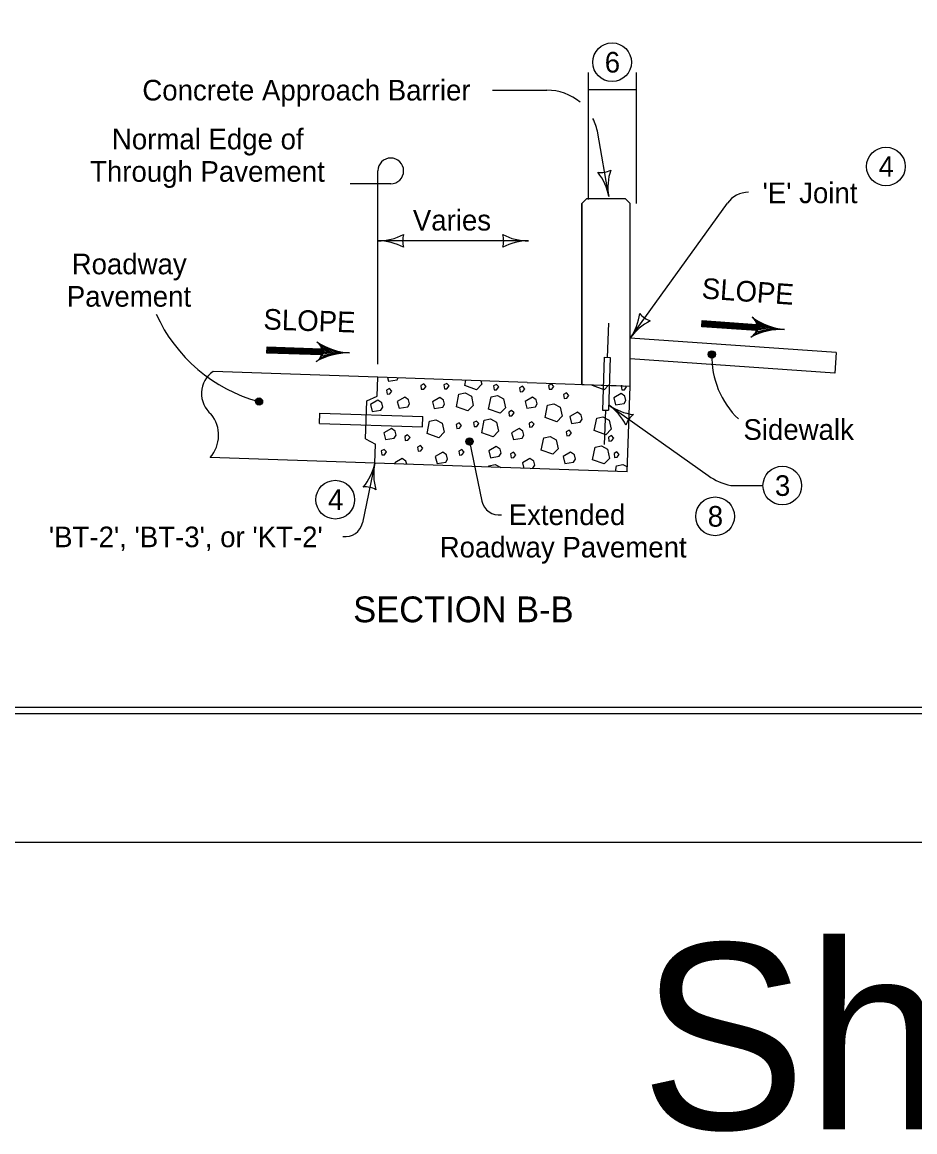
# Model space of a CAD drawing. Extents: x 10028 to 81668, y 6395 to 11634.
# Drawn here: x 10833 to 11525, y 7600 to 8460 of the extents above; entities that cross this region are included whole.
import ezdxf

# ---------------------------------------------------------------- set-up
doc = ezdxf.new("R2010")
doc.units = 0
for name, color, linetype in [('Default', 7, 'Continuous'), ('dsnCellElements', 7, 'Continuous'), ('dsnstdblockInterim', 7, 'Continuous'), ('dsnStdDimension', 7, 'Continuous'), ('dsnStdTextLabel', 7, 'Continuous'), ('ShtPlotIdentification', 7, 'Continuous')]:
    doc.layers.add(name, color=color, linetype=linetype)

msp = doc.modelspace()

# ---------------------------------------------------------------- linework, layer by layer
at = {"layer": 'Default'}
msp.add_lwpolyline([(10132.52, 9944.02), (13267.53, 9944.02), (13267.53, 7924.02), (10132.52, 7924.02)], close=True, dxfattribs=at)
msp.add_lwpolyline([(10132.52, 9944.02), (13267.53, 9944.02), (13267.53, 7924.02), (10132.52, 7924.02)], close=True, dxfattribs=at)
at = {"layer": 'dsnCellElements'}
for points in [[(11266.54, 8179.61), (11303.9, 8178.3), (11303.9, 8319.91), (11300.29, 8323.36), (11270.12, 8323.36), (11266.54, 8319.98)], [(11115.07, 8175.07), (11115.53, 8172.01), (11117.51, 8172.16), (11119.2, 8174.3), (11117.36, 8176.29)], [(11141.53, 8178.81), (11141.98, 8175.75), (11143.97, 8175.9), (11145.65, 8178.04), (11143.82, 8180.03)], [(11159.38, 8179.11), (11159.83, 8176.05), (11161.82, 8176.2), (11163.5, 8178.34), (11161.67, 8180.33)], [(11197.95, 8178.35), (11198.4, 8175.29), (11200.39, 8175.44), (11202.07, 8177.59), (11200.24, 8179.57)], [(11218.11, 8176.98), (11218.57, 8173.92), (11220.56, 8174.08), (11222.24, 8176.22), (11220.4, 8178.2)], [(11240.61, 8178.81), (11241.07, 8175.75), (11243.05, 8175.9), (11244.74, 8178.04), (11242.9, 8180.03)], [(11102.58, 8163.95), (11103.96, 8158.6), (11110.69, 8159.67), (11112.06, 8161.97), (11111.3, 8165.18), (11108.39, 8167.32)], [(11123.33, 8166.42), (11124.71, 8161.07), (11131.43, 8162.14), (11132.81, 8164.43), (11132.05, 8167.65), (11129.14, 8169.79)], [(11150.55, 8166.12), (11151.92, 8160.76), (11158.65, 8161.83), (11160.03, 8164.13), (11159.26, 8167.34), (11156.36, 8169.48)], [(11171.12, 8171.88), (11176.02, 8172.95), (11180.76, 8170.35), (11182.28, 8163.32), (11178.16, 8159.04), (11169.13, 8162.25)], [(11196.17, 8169.98), (11201.06, 8171.05), (11205.8, 8168.45), (11207.33, 8161.42), (11203.2, 8157.14), (11194.18, 8160.35)], [(11222.41, 8166.42), (11223.79, 8161.07), (11230.52, 8162.14), (11231.89, 8164.43), (11231.13, 8167.65), (11228.22, 8169.79)], [(11252.28, 8171.68), (11252.74, 8168.62), (11254.72, 8168.78), (11256.41, 8170.92), (11254.57, 8172.91)], [(11291.13, 8169.16), (11292.51, 8163.8), (11299.24, 8164.87), (11300.61, 8167.17), (11299.85, 8170.38), (11296.94, 8172.52)], [(11209.72, 8158.17), (11210.18, 8155.11), (11212.17, 8155.26), (11213.85, 8157.4), (11212.01, 8159.39)], [(11239.93, 8163.48), (11244.82, 8164.55), (11249.56, 8161.96), (11251.09, 8154.92), (11246.96, 8150.64), (11237.94, 8153.85)], [(11257.15, 8154.56), (11258.52, 8149.21), (11265.25, 8150.28), (11266.63, 8152.58), (11265.86, 8155.79), (11262.96, 8157.93)], [(11148.41, 8151.05), (11153.31, 8152.12), (11158.05, 8149.52), (11159.57, 8142.49), (11155.45, 8138.21), (11146.42, 8141.42)], [(11169.12, 8148.53), (11169.58, 8145.47), (11171.56, 8145.62), (11173.25, 8147.76), (11171.41, 8149.75)], [(11182.5, 8149.91), (11182.96, 8146.85), (11184.95, 8147), (11186.63, 8149.15), (11184.8, 8151.13)], [(11190.76, 8151.74), (11195.65, 8152.81), (11200.39, 8150.22), (11201.92, 8143.18), (11197.79, 8138.9), (11188.77, 8142.11)], [(11225.47, 8149.45), (11225.93, 8146.39), (11227.92, 8146.55), (11229.6, 8148.69), (11227.76, 8150.67)], [(11277.94, 8153.37), (11282.83, 8154.44), (11287.57, 8151.84), (11289.1, 8144.81), (11284.97, 8140.53), (11275.95, 8143.74)], [(11112.93, 8142.11), (11114.31, 8136.76), (11121.04, 8137.83), (11122.41, 8140.12), (11121.65, 8143.33), (11118.74, 8145.47)], [(11129.09, 8139.18), (11129.55, 8136.12), (11131.54, 8136.27), (11133.22, 8138.42), (11131.38, 8140.4)], [(11212.01, 8142.11), (11213.39, 8136.76), (11220.12, 8137.83), (11221.49, 8140.12), (11220.73, 8143.33), (11217.82, 8145.47)], [(11254.38, 8142.84), (11254.84, 8139.78), (11256.82, 8139.94), (11258.51, 8142.08), (11256.67, 8144.06)], [(11139.08, 8130.95), (11139.54, 8127.89), (11141.52, 8128.04), (11143.21, 8130.18), (11141.37, 8132.17)], [(11236.86, 8138.23), (11241.76, 8139.3), (11246.5, 8136.7), (11248.03, 8129.67), (11243.9, 8125.39), (11234.88, 8128.6)], [(11276.69, 8130.8), (11281.59, 8131.87), (11286.33, 8129.27), (11287.85, 8122.23), (11283.73, 8117.95), (11274.7, 8121.16)], [(11287.02, 8138.64), (11287.48, 8135.58), (11289.47, 8135.74), (11291.15, 8137.88), (11289.31, 8139.86)], [(11110.94, 8127.97), (11111.4, 8124.92), (11113.39, 8125.07), (11115.07, 8127.21), (11113.24, 8129.2)], [(11152.84, 8123.61), (11154.22, 8118.26), (11160.94, 8119.33), (11162.32, 8121.62), (11161.56, 8124.83), (11158.65, 8126.97)], [(11171.06, 8127.85), (11171.52, 8124.79), (11173.51, 8124.94), (11175.19, 8127.08), (11173.36, 8129.07)], [(11194.3, 8128.1), (11195.67, 8122.75), (11202.4, 8123.82), (11203.78, 8126.12), (11203.01, 8129.33), (11200.11, 8131.47)], [(11211.22, 8125.69), (11211.68, 8122.63), (11213.66, 8122.78), (11215.35, 8124.92), (11213.51, 8126.91)], [(11251.92, 8123.61), (11253.3, 8118.26), (11260.03, 8119.33), (11261.4, 8121.62), (11260.64, 8124.83), (11257.73, 8126.97)], [(11291.37, 8126.06), (11291.83, 8123), (11293.82, 8123.15), (11295.5, 8125.29), (11293.66, 8127.28)]]:
    msp.add_lwpolyline(points, close=True, dxfattribs=at)
for points in [[(11115.72, 8184.87), (11116.45, 8182.02)], [(11123.18, 8183.09), (11124.07, 8184.58)], [(11116.45, 8182.02), (11123.18, 8183.09)], [(11175.62, 8178.65), (11176.47, 8182.75)], [(11184.64, 8175.44), (11175.62, 8178.65)], [(11188.77, 8179.72), (11184.64, 8175.44)], [(11188.2, 8182.34), (11188.77, 8179.72)], [(11274.7, 8178.65), (11274.84, 8179.32)], [(11283.73, 8175.44), (11274.7, 8178.65)], [(11287.05, 8178.89), (11283.73, 8175.44)], [(11297.37, 8178.53), (11297.03, 8178.35)], [(11297.03, 8178.35), (11297.49, 8175.29)], [(11297.49, 8175.29), (11299.47, 8175.44)], [(11299.47, 8175.44), (11301.16, 8177.59)], [(11301.16, 8177.59), (11300.38, 8178.43)], [(11127.15, 8122.23), (11121.34, 8118.87)], [(11121.34, 8118.87), (11121.58, 8117.96)], [(11130.06, 8120.09), (11127.15, 8122.23)], [(11130.64, 8117.65), (11130.06, 8120.09)], [(11194.07, 8115.43), (11194.28, 8116.42)], [(11194.28, 8116.42), (11199.17, 8117.49)], [(11199.17, 8117.49), (11203.53, 8115.1)], [(11226.23, 8122.23), (11220.42, 8118.87)], [(11220.42, 8118.87), (11221.55, 8114.48)], [(11229.14, 8120.09), (11226.23, 8122.23)], [(11226.7, 8114.3), (11228.53, 8114.59)], [(11228.53, 8114.59), (11229.9, 8116.88)], [(11229.9, 8116.88), (11229.14, 8120.09)], [(11292.45, 8112), (11293.36, 8116.42)], [(11293.36, 8116.42), (11298.25, 8117.49)], [(11298.25, 8117.49), (11301.71, 8115.6)]]:
    msp.add_lwpolyline(points, dxfattribs=at)
at = {"layer": 'dsnstdblockInterim'}
for points in [[(10132.52, 9939.02), (13267.52, 9939.02), (13267.52, 7929.02), (10132.52, 7929.02)], [(10132.53, 9944.02), (13267.52, 9944.02), (13267.52, 7924.02), (10132.53, 7924.02)]]:
    msp.add_lwpolyline(points, close=True, dxfattribs=at)
at = {"layer": 'dsnStdDimension'}
msp.add_lwpolyline([(10028.02, 7824.52), (13372.02, 7824.52), (13372.02, 10408.52), (10028.02, 10408.52)], close=True, dxfattribs=at)
at = {"layer": 'ShtPlotIdentification'}
for p, q in [((11271.55, 8322.98), (11271.55, 8421.51)), ((11308.85, 8319.91), (11308.85, 8421.51)), ((11197.16, 8407.74), (11231.35, 8407.74)), ((11231.35, 8407.74), (11239.33, 8407.74)), ((11308.85, 8407.9), (11271.55, 8407.9)), ((11287.26, 8325.17), (11278.75, 8374.53)), ((11108.25, 8329.14), (11108.25, 8345.14)), ((11102.25, 8335.14), (11086.85, 8335.14)), ((11118.25, 8335.14), (11102.25, 8335.14)), ((11108.25, 8195.14), (11108.25, 8329.14)), ((11266.54, 8319.98), (11270.12, 8323.36)), ((11300.29, 8323.36), (11270.12, 8323.36)), ((11303.9, 8319.91), (11300.29, 8323.36)), ((11266.54, 8179.61), (11266.54, 8319.98)), ((11303.9, 8215.41), (11379.29, 8320.06)), ((11303.9, 8178.3), (11303.9, 8319.91)), ((11225.09, 8290.87), (11108.25, 8290.87)), ((11287.08, 8227.17), (11286.15, 8200.52)), ((11402, 8223.66), (11359.67, 8226.62)), ((11401.7, 8221.11), (11401.7, 8221.11)), ((11402.09, 8226.06), (11402.09, 8226.06)), ((11463.7, 8204.24), (11303.9, 8215.41)), ((11064.71, 8204.8), (11022.3, 8206.28)), ((11064.49, 8202.25), (11064.49, 8202.25)), ((11064.71, 8207.2), (11064.71, 8207.2)), ((11283.8, 8200.61), (11282.37, 8159.67)), ((11283.8, 8200.61), (11288.5, 8200.44)), ((11463.7, 8204.24), (11462.58, 8188.27)), ((11288.5, 8200.44), (11287.07, 8159.51)), ((11462.58, 8188.27), (11303.9, 8199.37)), ((11108.25, 8185.14), (10980.51, 8189.6)), ((11107.74, 8170.48), (11108.25, 8185.14)), ((11223.95, 8181.1), (11108.25, 8185.14)), ((11223.95, 8181.09), (11283.05, 8179.03)), ((11287.75, 8178.87), (11303.9, 8178.3)), ((11301.58, 8111.68), (11303.9, 8178.3)), ((11098.58, 8137.45), (11099.61, 8166.76)), ((11099.61, 8166.76), (11107.74, 8170.48)), ((11282.37, 8159.67), (11287.07, 8159.51)), ((11284.72, 8159.59), (11283.79, 8132.94)), ((11287.22, 8163.66), (11364.47, 8108.85)), ((11062.98, 8149.37), (11063.26, 8157.36)), ((11062.98, 8149.37), (11142.93, 8146.57)), ((11063.26, 8157.36), (11143.21, 8154.57)), ((11142.93, 8146.57), (11143.21, 8154.57)), ((11098.58, 8137.45), (11106.44, 8133.17)), ((11105.93, 8118.51), (11106.44, 8133.17)), ((11179.38, 8135.33), (11188.92, 8089.07)), ((11105.93, 8118.51), (10978.18, 8122.97)), ((11105.93, 8118.51), (11096.39, 8072.25)), ((11301.58, 8111.68), (11105.93, 8118.51)), ((11382.06, 8101.11), (11406.85, 8101.11))]:
    msp.add_line(p, q, dxfattribs=at)
for points in [[(11401.75, 8221.27), (11359.5, 8224.22), (11359.83, 8229.01), (11402.09, 8226.06), (11401.67, 8221.97), (11360.08, 8224.72), (11360.46, 8228.52), (11401.12, 8225.51), (11401.02, 8222.65), (11360.71, 8225.31), (11360.99, 8227.84), (11400.55, 8225.07), (11400.53, 8223.27), (11361.22, 8225.81), (11361.37, 8227.23), (11399.98, 8224.48)], [(11400.39, 8218.23), (11402.39, 8220.96), (11402.9, 8225.12), (11401.62, 8228.88), (11407.68, 8225.85), (11414.83, 8223.23), (11416.86, 8222.6), (11411.49, 8221.92), (11403.64, 8219.81), (11401.28, 8218.75), (11402.75, 8227.58), (11413.75, 8222.98), (11402.51, 8220.42), (11403.37, 8226.52), (11410.89, 8223.13), (11403.68, 8221.88), (11403.61, 8225.44), (11408.42, 8223.51), (11404.59, 8222.72), (11404.49, 8224.43), (11406.26, 8223.77)], [(11063.29, 8199.32), (11065.19, 8202.12), (11065.55, 8206.3), (11064.14, 8210.01), (11070.3, 8207.19), (11077.54, 8204.82), (11079.59, 8204.27), (11074.26, 8203.39), (11066.48, 8201.01), (11064.16, 8199.87), (11065.32, 8208.75), (11076.47, 8204.54), (11065.33, 8201.58), (11065.97, 8207.71), (11073.61, 8204.58), (11066.45, 8203.08), (11066.25, 8206.64), (11071.13, 8204.88), (11067.33, 8203.95), (11067.17, 8205.66), (11068.96, 8205.06)], [(11064.54, 8202.4), (11022.21, 8203.88), (11022.38, 8208.68), (11064.71, 8207.2), (11064.43, 8203.1), (11022.78, 8204.4), (11023.02, 8208.21), (11063.76, 8206.62), (11063.77, 8203.76), (11023.38, 8205.01), (11023.58, 8207.55), (11063.21, 8206.17), (11063.26, 8204.36), (11023.88, 8205.52), (11023.98, 8206.95), (11062.66, 8205.55)], [(11366.96, 8200.29), (11367.9, 8200.71), (11369.37, 8201.17), (11369.66, 8202.66), (11369.46, 8203.97), (11368.51, 8205.18), (11367.12, 8205.05), (11365.64, 8204.85), (11364.94, 8203.67), (11364.81, 8202.43), (11365.68, 8200.81), (11366.75, 8200.68), (11368.22, 8201.05), (11369.43, 8201.99), (11369.39, 8203.39), (11368.45, 8204.52), (11367.13, 8204.64), (11365.66, 8204.35), (11365.43, 8203.52), (11365.13, 8202.53), (11365.83, 8201.31), (11366.9, 8201.34), (11368.13, 8201.54), (11369.01, 8202.23), (11368.56, 8203.45), (11367.64, 8204.16), (11366.4, 8204.21), (11366.09, 8203.54), (11365.7, 8202.79), (11366.31, 8201.82), (11367.22, 8201.6), (11368.03, 8202.03), (11368.09, 8202.94), (11367.66, 8203.59), (11366.83, 8203.81), (11366.42, 8203.47), (11366.19, 8202.97), (11366.62, 8202.24), (11367.2, 8202.09), (11367.77, 8202.44), (11367.67, 8202.93), (11367.25, 8203.25), (11366.68, 8203.23), (11366.69, 8202.82), (11367.19, 8202.59)], [(11015.92, 8163.7), (11016.86, 8164.12), (11018.33, 8164.58), (11018.62, 8166.07), (11018.42, 8167.38), (11017.48, 8168.59), (11016.08, 8168.47), (11014.6, 8168.26), (11013.9, 8167.08), (11013.77, 8165.84), (11014.64, 8164.22), (11015.71, 8164.09), (11017.18, 8164.46), (11018.39, 8165.4), (11018.35, 8166.8), (11017.41, 8167.93), (11016.09, 8168.05), (11014.62, 8167.76), (11014.39, 8166.93), (11014.09, 8165.94), (11014.79, 8164.72), (11015.86, 8164.75), (11017.09, 8164.95), (11017.97, 8165.64), (11017.52, 8166.86), (11016.6, 8167.57), (11015.36, 8167.62), (11015.05, 8166.95), (11014.66, 8166.2), (11015.27, 8165.23), (11016.18, 8165.01), (11016.99, 8165.44), (11017.05, 8166.35), (11016.62, 8167), (11015.79, 8167.22), (11015.38, 8166.88), (11015.15, 8166.38), (11015.58, 8165.65), (11016.16, 8165.5), (11016.73, 8165.85), (11016.64, 8166.34), (11016.21, 8166.66), (11015.64, 8166.64), (11015.65, 8166.23), (11016.15, 8166)], [(11179.16, 8132.76), (11180.11, 8133.19), (11181.57, 8133.64), (11181.86, 8135.13), (11181.66, 8136.44), (11180.72, 8137.65), (11179.32, 8137.53), (11177.85, 8137.32), (11177.14, 8136.15), (11177.01, 8134.91), (11177.88, 8133.29), (11178.95, 8133.15), (11180.43, 8133.53), (11181.63, 8134.47), (11181.59, 8135.87), (11180.65, 8136.99), (11179.33, 8137.12), (11177.86, 8136.83), (11177.64, 8136), (11177.34, 8135), (11178.03, 8133.79), (11179.1, 8133.82), (11180.33, 8134.02), (11181.21, 8134.7), (11180.77, 8135.93), (11179.84, 8136.64), (11178.6, 8136.69), (11178.29, 8136.02), (11177.9, 8135.27), (11178.51, 8134.29), (11179.42, 8134.07), (11180.23, 8134.51), (11180.29, 8135.42), (11179.86, 8136.06), (11179.03, 8136.29), (11178.63, 8135.94), (11178.39, 8135.44), (11178.83, 8134.72), (11179.41, 8134.57), (11179.97, 8134.91), (11179.88, 8135.41), (11179.46, 8135.72), (11178.88, 8135.7), (11178.89, 8135.29), (11179.39, 8135.06)]]:
    msp.add_lwpolyline(points, dxfattribs=at)
for centre, radius in [((11289.9, 8429.4), 15), ((11502.18, 8348.56), 15), ((11367.18, 8202.86), 2.8), ((11016.14, 8166.27), 2.8), ((11179.38, 8135.33), 2.8), ((11421.85, 8101.11), 15), ((11075.27, 8090.18), 15), ((11369.77, 8077.26), 15)]:
    msp.add_circle(centre, radius, dxfattribs=at)
for centre, radius, start, end in [((11239.33, 8367.74), 40, 49.89102, 90), ((11239.33, 8367.74), 40, 9.78205, 26.74574), ((11118.25, 8345.14), 10, 270, 180), ((11281.21, 8360.29), 16.42, 262.04882, 297.51553), ((11281.21, 8360.29), 16.42, 262.04882, 297.51553), ((11245.38, 8317.95), 42.5, 9.78218, 37.85466), ((11245.38, 8317.95), 42.5, 9.78218, 37.85466), ((11329.15, 8332.39), 42.5, 161.70969, 189.78217), ((11329.15, 8332.39), 42.5, 161.70969, 189.78217), ((11395.63, 8308.53), 20, 90, 144.80599), ((11108.25, 8333.37), 42.5, 270, 298.07249), ((11143.89, 8290.87), 16.42, 162.26665, 197.73335), ((11189.45, 8290.87), 16.42, 342.26665, 17.73335), ((11225.09, 8333.37), 42.5, 241.92751, 270), ((11189.45, 8290.87), 16.42, 342.26665, 17.73335), ((11225.09, 8333.37), 42.5, 241.92751, 270), ((11108.25, 8248.37), 42.5, 61.92751, 90), ((11225.09, 8248.37), 42.5, 90, 118.07249), ((11225.09, 8248.37), 42.5, 90, 118.07249), ((11048.06, 8284.58), 122.54, 204.30911, 254.90087), ((11269.17, 8239.91), 42.5, 324.80609, 352.87858), ((11269.17, 8239.91), 42.5, 324.80609, 352.87858), ((11338.63, 8190.92), 42.5, 116.7336, 144.80609), ((11338.63, 8190.92), 42.5, 116.7336, 144.80609), ((11324.44, 8244.53), 16.42, 217.07274, 252.53944), ((11324.44, 8244.53), 16.42, 217.07274, 252.53944), ((11393.24, 8224.27), 9.03, 297.71363, 54.28426), ((11428.62, 8273.48), 51.58, 234.28469, 264.31472), ((11421.43, 8170.61), 51.58, 87.68318, 117.71321), ((11055.93, 8205.11), 9.03, 299.71442, 56.28506), ((11089.57, 8255.52), 51.58, 236.28548, 266.31551), ((11085.97, 8152.47), 51.58, 89.68397, 119.714), ((11434.35, 8201.28), 67.19, 178.65758, 226.20268), ((10992.42, 8172.49), 20.85, 124.83209, 230.03769), ((11311.78, 8198.34), 42.5, 234.70019, 262.77268), ((11262.66, 8128.97), 42.5, 26.6277, 54.70019), ((10959.13, 8140.23), 25.71, 317.82833, 39.2857), ((11316.3, 8143.07), 16.42, 126.96684, 162.43354), ((11064.3, 8127.09), 42.5, 320.27547, 348.34796), ((11147.55, 8109.93), 42.5, 168.34796, 196.42045), ((11392.2, 8148.03), 48, 234.7002, 257.80251), ((11098.73, 8083.61), 16.42, 60.61461, 96.08131), ((11202.36, 8092.14), 13.79, 192.84478, 277.46606), ((11082.94, 8075.32), 13.79, 262.53394, 347.15522)]:
    msp.add_arc(centre, radius, start, end, dxfattribs=at)

# ---------------------------------------------------------------- texts
at = {"layer": 'dsnCellElements'}
for s, height, p in [('Concrete Approach Barrier', 16, (10925.68, 8399.74)), ('Normal Edge of', 16, (10902.07, 8361.84)), ('4', 16, (11496.51, 8340.56)), ('Through Pavement', 16, (10885.15, 8336.7)), ("'E' Joint", 16, (11406.55, 8320.11)), ('Varies', 16, (11135.42, 8298.91)), ('Roadway', 16, (10870.89, 8264.97)), ('Pavement', 16, (10867.15, 8239.83)), ('Sidewalk', 16, (11391.73, 8136.57)), ('3', 16, (11416.14, 8093.11)), ('4', 16, (11069.6, 8082.18)), ('Extended ', 16, (11209.73, 8070.49)), ("'BT-2', 'BT-3', or 'KT-2'", 16, (10853.21, 8053.31)), ('Roadway Pavement', 16, (11156.22, 8045.35)), ('SECTION B-B', 20, (11089.15, 7995.12))]:
    msp.add_text(s, height=height, dxfattribs=at).set_placement(p)
for rotation, p in [(355.99918, (11359, 8246.23)), (358, (11019.36, 8222.23))]:
    msp.add_text('SLOPE', height=16, rotation=rotation, dxfattribs=at).set_placement(p)
at = {"layer": 'dsnStdTextLabel'}
msp.add_text('Sheet 1', height=144, dxfattribs=at).set_placement((11311.87, 7602.02))
at = {"layer": 'ShtPlotIdentification'}
for s, p in [('6', (11284.19, 8421.4)), ('8', (11364.04, 8069.26))]:
    msp.add_text(s, height=16, dxfattribs=at).set_placement(p)

doc.saveas('drawing.dxf')
